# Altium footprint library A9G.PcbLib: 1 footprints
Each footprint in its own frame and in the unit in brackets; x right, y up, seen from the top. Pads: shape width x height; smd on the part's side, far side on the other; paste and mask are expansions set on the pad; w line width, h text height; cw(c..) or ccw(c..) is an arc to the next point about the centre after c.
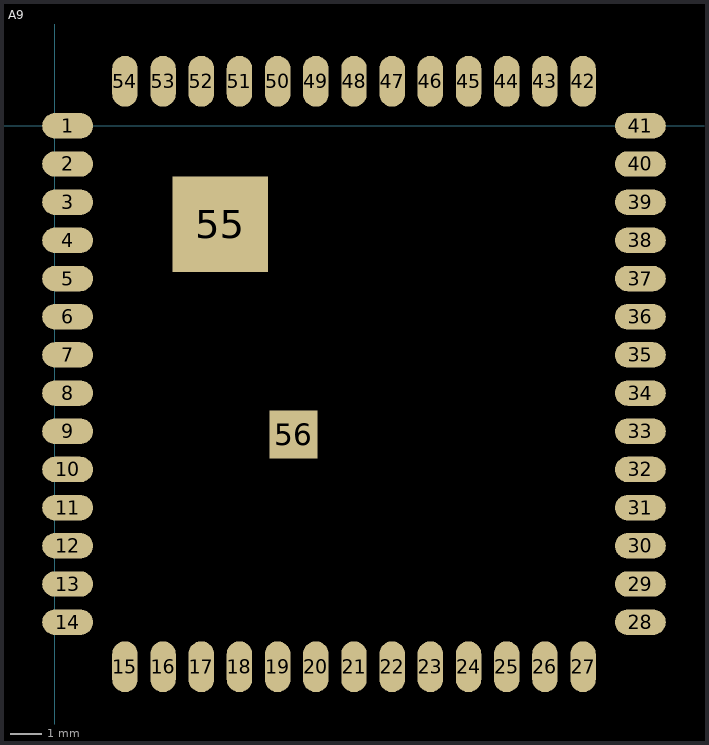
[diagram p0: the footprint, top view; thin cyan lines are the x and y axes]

## A9 [mm]
pads (56):
  oval 1.6x0.8 smd: 1(0.4,0) 2(0.4,-1.2) 3(0.4,-2.4) 4(0.4,-3.6) 5(0.4,-4.8) 6(0.4,-6) 7(0.4,-7.2) 8(0.4,-8.4) 9(0.4,-9.6) 10(0.4,-10.8) 11(0.4,-12) 12(0.4,-13.2) 13(0.4,-14.4) 14(0.4,-15.6) 28(18.4,-15.6) 29(18.4,-14.4) 30(18.4,-13.2) 31(18.4,-12) 32(18.4,-10.8) 33(18.4,-9.6) 34(18.4,-8.4) 35(18.4,-7.2) 36(18.4,-6) 37(18.4,-4.8) 38(18.4,-3.6) 39(18.4,-2.4) 40(18.4,-1.2) 41(18.4,0)
  oval 0.8x1.6 smd: 15(2.2,-17) 16(3.4,-17) 17(4.6,-17) 18(5.8,-17) 19(7,-17) 20(8.2,-17) 21(9.4,-17) 22(10.6,-17) 23(11.8,-17) 24(13,-17) 25(14.2,-17) 26(15.4,-17) 27(16.6,-17) 42(16.6,1.4) 43(15.4,1.4) 44(14.2,1.4) 45(13,1.4) 46(11.8,1.4) 47(10.6,1.4) 48(9.4,1.4) 49(8.2,1.4) 50(7,1.4) 51(5.8,1.4) 52(4.6,1.4) 53(3.4,1.4) 54(2.2,1.4)
  rect 3x3 smd: 55(5.2,-3.1)
  rect 1.5x1.5 smd: 56(7.5,-9.7)
3D body "a9.step": height 1.8, standoff -0.16, extent 0,-17.4 18.8,1.8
